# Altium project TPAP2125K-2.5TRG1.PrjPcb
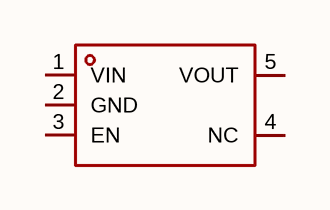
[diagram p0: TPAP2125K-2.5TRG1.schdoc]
1 sheet, 1 parts. Net scope: global (net labels, ports and power ports of the same name join across sheets).

## Sheet TPAP2125K-2.5TRG1.schdoc
size 127 x 101 mm

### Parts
U?  tpap2125k-2.5trg1  [SOT-23-5_L2.9-W1.6-P0.95-LS2.8-BL]  (value not drawn)

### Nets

Not connected (* = marked no-connect by the designer): U? 1(VIN) 2(GND) 3(EN) 4(NC) 5(VOUT)

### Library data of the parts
U? = tpap2125k-2.5trg1: 输出极性:正极;工作电压:7V;输出电压:2.5V;输出电流:300mA;电源纹波抑制比(PSRR):70dB@(1kHz);输出类型:固定;; Manufacturer: TECH PUBLIC(台舟); AddInBom: yes; ModelId: 018c57e721114987ae90467fe9f1d259; ModelTransform: 114.96,110.236,0,0,0,0,0,0,0; Output Configuration: 正极; Voltage - Supply: 7V; Output Voltage: 2.5V; Output Current: 300mA; standby current: 800nA; Output Type: 固定; Number of Outputs: 1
